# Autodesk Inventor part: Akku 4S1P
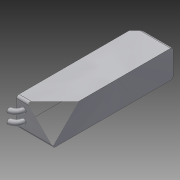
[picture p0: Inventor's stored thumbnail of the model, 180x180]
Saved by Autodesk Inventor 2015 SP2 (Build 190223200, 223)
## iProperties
Created: 2012-08
Part Number: Akku 4S1P
Material: LCP-Kunststoff
Document SubType Name: Modeling
Designer: rYan
Mass: 112.412 g
Surface Area: 121.07 cm^2
Volume: 69.1339 cm^3
Density: 1.626 g/cm^3
Description: TP1300-4SPR45
Vendor: Thunder Power
Appearance: Glatt - weiß
Author: rYan
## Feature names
1. Extrusion1
2. Rundung1 [Fillet]
3. Sweeping3
4. Spiegeln2 [Mirror]
## Parameters: d3 = 23 mm, d4 = 0, d5 = 2 mm, d26 = 4 mm, d27 = 6 mm, d30 = 4 mm, d32 = 0, d33 = 0
